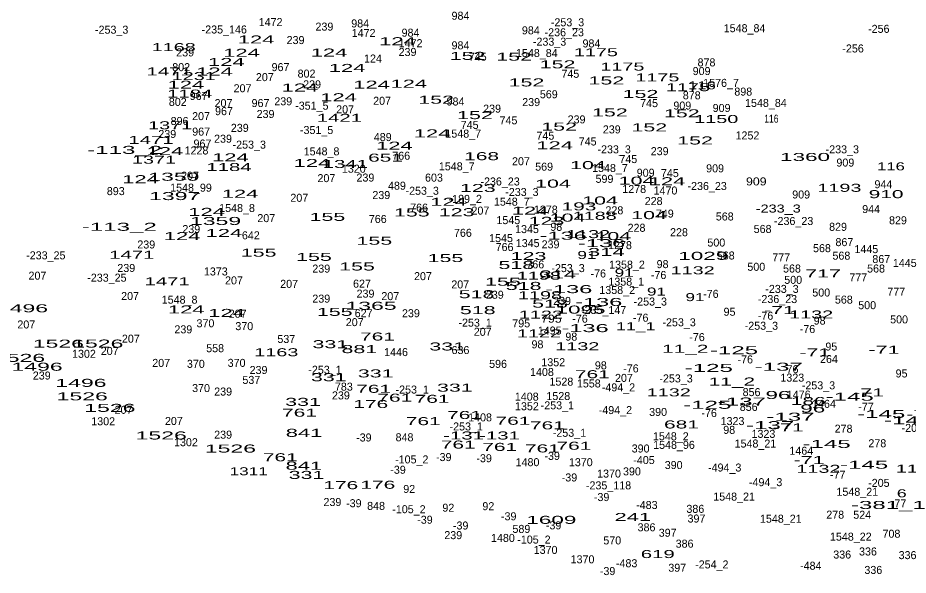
# Model space of a CAD drawing. Extents: x -660434 to -656144, y -997850 to -994016.
# Drawn here: x -659474 to -659029.2, y -994854.6 to -994576.2 of the extents above; entities that cross this region are included whole.
import ezdxf
from ezdxf.enums import TextEntityAlignment as Align

# ---------------------------------------------------------------- set-up
doc = ezdxf.new("R2010")
doc.units = 0
doc.header["$LTSCALE"] = 1.6
doc.layers.add('24', color=7, linetype='Continuous')

msp = doc.modelspace()

# ---------------------------------------------------------------- texts
at = {"layer": '24'}
for s, p in [('984', (-659252.897, -994577.15)), ('1472', (-659347.76, -994580.3)), ('239', (-659320.873, -994582.58)), ('984', (-659303.007, -994581)), ('-253_3', (-659199.422, -994580.42)), ('-253_3', (-659427.162, -994584.13)), ('-235_146', (-659370.905, -994584.02)), ('1472', (-659301.3, -994585.77)), ('984', (-659277.857, -994585.61)), ('984', (-659217.757, -994584.45)), ('-236_23', (-659201.057, -994585.42)), ('1548_84', (-659110.977, -994583.38)), ('-256', (-659043.91, -994583.7)), ('239', (-659335.293, -994589.31)), ('1472', (-659277.81, -994590.86)), ('984', (-659252.897, -994591.94)), ('-233_3', (-659208.392, -994590.11)), ('984', (-659187.467, -994590.99)), ('239', (-659390.463, -994595.47)), ('239', (-659279.353, -994595.28)), ('1548_84', (-659214.757, -994595.77)), ('-256', (-659056.77, -994593.5)), ('124', (-659296.62, -994598.52)), ('745', (-659244.277, -994597.6)), ('878', (-659129.993, -994600.46)), ('802', (-659392.431, -994602.84)), ('967', (-659342.813, -994602.82)), ('909', (-659132.432, -994604.79)), ('207', (-659350.647, -994607.82)), ('802', (-659329.801, -994606.06)), ('745', (-659198.007, -994606.15)), ('207', (-659361.787, -994613.39)), ('239', (-659327.023, -994611.43)), ('1576_7', (-659122.725, -994610.69)), ('967', (-659383.713, -994617.23)), ('569', (-659208.788, -994616.39)), ('878', (-659137.373, -994616.89)), ('898', (-659111.623, -994615.05)), ('802', (-659394.141, -994620.21)), ('207', (-659371.287, -994620.79)), ('967', (-659352.803, -994620.78)), ('239', (-659341.443, -994619.89)), ('-351_5', (-659327.166, -994622.09)), ('207', (-659292.067, -994619.64)), ('984', (-659255.387, -994619.99)), ('239', (-659217.593, -994620.29)), ('745', (-659158.677, -994620.81)), ('909', (-659142.082, -994622.03)), ('909', (-659122.442, -994623.23)), ('1548_84', (-659100.317, -994620.71)), ('207', (-659382.517, -994627.32)), ('967', (-659371.043, -994624.82)), ('239', (-659350.283, -994626.24)), ('207', (-659310.547, -994623.91)), ('239', (-659237.103, -994623.56)), ('896', (-659393.228, -994629.73)), ('745', (-659248.307, -994631.69)), ('745', (-659228.917, -994629.39)), ('239', (-659194.903, -994628.94)), ('239', (-659399.393, -994636.23)), ('967', (-659382.463, -994635.04)), ('239', (-659363.163, -994633.16)), ('-351_5', (-659324.766, -994634.24)), ('1548_7', (-659251.518, -994636.05)), ('239', (-659177.313, -994633.94)), ('967', (-659381.803, -994641)), ('239', (-659371.533, -994638.59)), ('489', (-659291.737, -994637.76)), ('745', (-659210.487, -994637.07)), ('745', (-659189.367, -994639.95)), ('1252', (-659109.53, -994636.94)), ('1228', (-659384.79, -994644.46)), ('-253_3', (-659358.422, -994641.54)), ('1548_8', (-659322.303, -994644.91)), ('-233_3', (-659176.132, -994643.9)), ('239', (-659153.393, -994644.81)), ('-233_3', (-659062.142, -994643.9)), ('766', (-659282.513, -994647.09)), ('207', (-659222.687, -994649.84)), ('745', (-659169.047, -994648.75)), ('1320', (-659306.214, -994653.57)), ('1548_7', (-659254.778, -994652.38)), ('569', (-659211.118, -994652.55)), ('1548_7', (-659178.218, -994653.22)), ('909', (-659125.712, -994653.39)), ('909', (-659060.622, -994650.51)), ('207', (-659388.037, -994657.07)), ('207', (-659319.877, -994658.29)), ('239', (-659300.393, -994657.99)), ('603', (-659266.147, -994658.02)), ('599', (-659180.968, -994658.62)), ('909', (-659160.382, -994655.58)), ('745', (-659148.307, -994655.77)), ('1548_99', (-659387.533, -994663.05)), ('489', (-659284.637, -994662.06)), ('-236_23', (-659233.117, -994659.95)), ('-236_23', (-659129.667, -994662.22)), ('944', (-659041.601, -994661.34)), ('893', (-659425.113, -994664.76)), ('239', (-659292.463, -994666.74)), ('-253_3', (-659272.022, -994664.59)), ('-233_3', (-659222.212, -994665.22)), ('1278', (-659166.116, -994663.71)), ('1470', (-659150.484, -994664.46)), ('909', (-659082.702, -994666.45)), ('207', (-659333.417, -994668.09)), ('-189_2', (-659250.522, -994668.64)), ('1548_7', (-659227.278, -994670.03)), ('228', (-659156.407, -994669.73)), ('1548_8', (-659364.523, -994673.2)), ('766', (-659273.583, -994673.01)), ('207', (-659242.937, -994674.5)), ('1278', (-659210.276, -994673.99)), ('228', (-659175.997, -994674.34)), ('749', (-659150.823, -994675.99)), ('944', (-659047.741, -994673.73)), ('207', (-659349.927, -994678.27)), ('766', (-659294.223, -994678.68)), ('1545', (-659228.994, -994679.25)), ('568', (-659120.883, -994677.43)), ('-236_23', (-659086.467, -994679.7)), ('829', (-659034.333, -994679.33)), ('239', (-659387.393, -994683.74)), ('766', (-659251.693, -994685.61)), ('1345', (-659219.674, -994683.73)), ('98', (-659205.023, -994682.61)), ('228', (-659164.947, -994683.08)), ('228', (-659143.737, -994685.29)), ('568', (-659101.963, -994683.66)), ('829', (-659064.283, -994682.6)), ('642', (-659357.637, -994686.85)), ('1545', (-659232.644, -994688.23)), ('239', (-659409.883, -994691.43)), ('766', (-659230.873, -994692.71)), ('1345', (-659219.334, -994690.74)), ('239', (-659207.913, -994691.35)), ('1278', (-659173.216, -994691.76)), ('500', (-659125.085, -994690.46)), ('568', (-659072.303, -994693.26)), ('867', (-659061.108, -994690.25)), ('1445', (-659050.139, -994693.74)), ('-233_25', (-659460.061, -994696.85)), ('568', (-659120.383, -994696.93)), ('777', (-659092.663, -994697.84)), ('568', (-659062.603, -994697.01)), ('867', (-659042.678, -994698.7)), ('239', (-659419.873, -994703.16)), ('766', (-659215.523, -994701.36)), ('-253_3', (-659199.162, -994703.22)), ('1358_2', (-659169.719, -994701.49)), ('98', (-659151.933, -994701.24)), ('500', (-659105.115, -994702.56)), ('568', (-659087.283, -994703.44)), ('568', (-659045.293, -994703.43)), ('1445', (-659030.939, -994700.65)), ('207', (-659464.237, -994706.99)), ('1373', (-659375.136, -994704.9)), ('239', (-659322.453, -994703.47)), ('207', (-659271.647, -994707.25)), ('-76', (-659184.065, -994705.91)), ('-76', (-659153.925, -994706.67)), ('-233_25', (-659429.541, -994708)), ('207', (-659366.057, -994709.36)), ('207', (-659338.497, -994711.09)), ('627', (-659302.108, -994711.01)), ('207', (-659253.017, -994711.38)), ('1358_1', (-659170.093, -994709.98)), ('500', (-659086.685, -994709.09)), ('777', (-659054.193, -994707.9)), ('239', (-659300.343, -994715.97)), ('239', (-659235.753, -994716.54)), ('1358_2', (-659174.609, -994714.16)), ('-76', (-659127.815, -994716.09)), ('-233_3', (-659092.282, -994713.62)), ('500', (-659072.665, -994715.43)), ('777', (-659035.183, -994715.01)), ('207', (-659417.967, -994717.17)), ('1548_8', (-659393.223, -994718.99)), ('239', (-659322.453, -994718.47)), ('207', (-659287.967, -994717.23)), ('239', (-659202.153, -994719.62)), ('-253_3', (-659158.072, -994719.93)), ('-236_23', (-659094.527, -994718.69)), ('568', (-659061.383, -994718.97)), ('-235_147', (-659181.365, -994724.16)), ('95', (-659118.483, -994725.03)), ('500', (-659049.725, -994721.75)), ('207', (-659364.207, -994726.01)), ('627', (-659301.288, -994725.76)), ('239', (-659277.663, -994725.77)), ('-76', (-659193.185, -994728.48)), ('-76', (-659162.855, -994727.99)), ('-76', (-659100.485, -994727.02)), ('98', (-659073.473, -994729.45)), ('500', (-659033.785, -994728.85)), ('207', (-659469.807, -994731.38)), ('239', (-659391.353, -994733.82)), ('370', (-659380.307, -994730.79)), ('370', (-659360.907, -994732.23)), ('207', (-659305.737, -994730.23)), ('-253_1', (-659245.586, -994730.48)), ('795', (-659222.568, -994730.81)), ('1495', (-659208.31, -994734.41)), ('-253_3', (-659143.672, -994730.3)), ('-253_3', (-659102.582, -994732.03)), ('-76', (-659079.555, -994733.65)), ('207', (-659417.587, -994738.49)), ('537', (-659339.913, -994738.63)), ('207', (-659241.797, -994735.03)), ('98', (-659197.523, -994737.46)), ('-76', (-659134.725, -994737.69)), ('558', (-659375.477, -994743.24)), ('98', (-659214.433, -994741.31)), ('95', (-659067.633, -994742.41)), ('1302', (-659441.004, -994746.03)), ('207', (-659428.147, -994744.64)), ('1446', (-659285.094, -994745.19)), ('636', (-659252.908, -994744.16)), ('207', (-659402.417, -994750.59)), ('370', (-659385.107, -994751.05)), ('370', (-659364.747, -994750.57)), ('596', (-659234.128, -994751.06)), ('1352', (-659206.55, -994750.25)), ('98', (-659182.783, -994751.81)), ('-76', (-659110.625, -994748.83)), ('264', (-659068.827, -994748.65)), ('239', (-659353.783, -994754.13)), ('-253_1', (-659320.586, -994754.01)), ('1408', (-659212.198, -994755.13)), ('-76', (-659167.745, -994753.34)), ('-76', (-659087.915, -994753.72)), ('95', (-659032.543, -994755.84)), ('239', (-659462.093, -994756.9)), ('537', (-659357.383, -994759.09)), ('1528', (-659202.49, -994759.93)), ('1558', (-659188.8, -994760.85)), ('207', (-659171.237, -994758.08)), ('-253_3', (-659145.212, -994758.34)), ('1323', (-659087.13, -994757.94)), ('370', (-659382.507, -994763.15)), ('239', (-659371.473, -994764.9)), ('783', (-659311.173, -994762.44)), ('-253_1', (-659277.006, -994763.9)), ('-494_2', (-659173.966, -994762.81)), ('856', (-659107.483, -994765.17)), ('-253_3', (-659074.052, -994761.8)), ('239', (-659312.643, -994766.82)), ('1408', (-659219.788, -994767.43)), ('1528', (-659204.03, -994767.14)), ('1476', (-659083.925, -994766.41)), ('207', (-659421.227, -994774.02)), ('1352', (-659219.71, -994772.24)), ('-253_1', (-659204.506, -994771.78)), ('-494_2', (-659175.506, -994774.15)), ('856', (-659108.923, -994772.57)), ('1464', (-659071.304, -994771.03)), ('-77', (-659050.315, -994772.51)), ('1408', (-659243.118, -994777.8)), ('390', (-659154.177, -994775.1)), ('-76', (-659128.675, -994775.62)), ('1302', (-659431.404, -994779.74)), ('207', (-659396.077, -994779.59)), ('-253_1', (-659250.026, -994782.33)), ('1323', (-659116.99, -994779.64)), ('278', (-659061.513, -994783.45)), ('-205', (-659027.179, -994783.06)), ('239', (-659371.473, -994786.44)), ('-39', (-659301.18, -994787.84)), ('848', (-659280.861, -994787.74)), ('-253_1', (-659198.466, -994785.5)), ('1548_2', (-659147.813, -994787.24)), ('98', (-659118.653, -994784.04)), ('1323', (-659101.55, -994786.02)), ('1302', (-659390.054, -994790.21)), ('1548_96', (-659146.233, -994791.54)), ('1548_21', (-659105.546, -994790.86)), ('278', (-659044.653, -994790.72)), ('390', (-659162.907, -994793.34)), ('1464', (-659082.634, -994794.46)), ('-105_2', (-659277.24, -994798.8)), ('-39', (-659261.25, -994797.63)), ('-39', (-659241.09, -994798.21)), ('1480', (-659219.408, -994800.18)), ('-39', (-659207.1, -994797.06)), ('1370', (-659192.8, -994800.2)), ('-405', (-659161.213, -994799.12)), ('-39', (-659284.1, -994803.97)), ('390', (-659167.237, -994804.78)), ('390', (-659146.397, -994801.61)), ('-494_3', (-659120.896, -994802.86)), ('-39', (-659198.45, -994807.81)), ('1370', (-659178.68, -994805.87)), ('-494_3', (-659100.446, -994810.16)), ('-77', (-659064.425, -994806.41)), ('92', (-659278.513, -994813.56)), ('-235_118', (-659178.929, -994811.77)), ('-205', (-659043.879, -994810.52)), ('-39', (-659182.38, -994817.61)), ('1548_21', (-659116.196, -994817.37)), ('1548_21', (-659054.656, -994814.97)), ('239', (-659316.883, -994820.09)), ('-39', (-659306.18, -994820.68)), ('848', (-659295.071, -994822.02)), ('92', (-659258.973, -994822.93)), ('92', (-659238.983, -994822.16)), ('-483', (-659159.789, -994821.56)), ('386', (-659135.573, -994823.49)), ('-77', (-659034.035, -994820.79)), ('-105_2', (-659278.65, -994823.68)), ('-39', (-659228.8, -994827.21)), ('278', (-659065.683, -994826.4)), ('524', (-659052.201, -994826.44)), ('-39', (-659270.65, -994828.94)), ('-39', (-659252.8, -994831.82)), ('-39', (-659206.38, -994831.73)), ('397', (-659134.998, -994828.33)), ('1548_21', (-659092.866, -994828.42)), ('239', (-659256.513, -994836.63)), ('589', (-659222.473, -994833.51)), ('386', (-659159.953, -994832.71)), ('397', (-659149.398, -994835.43)), ('708', (-659037.597, -994835.92)), ('1480', (-659231.698, -994838.02)), ('-105_2', (-659216.2, -994838.84)), ('570', (-659177.067, -994839.26)), ('386', (-659140.943, -994840.88)), ('1548_22', (-659057.902, -994837.38)), ('1370', (-659210.37, -994844)), ('336', (-659049.323, -994844.79)), ('1370', (-659191.93, -994848.7)), ('336', (-659062.193, -994846.32)), ('336', (-659029.553, -994846.61)), ('-39', (-659179.41, -994854.58)), ('-483', (-659169.879, -994850.66)), ('397', (-659144.598, -994852.91)), ('-254_2', (-659127.337, -994851.26)), ('-484', (-659077.903, -994851.91)), ('336', (-659046.643, -994854.01))]:
    msp.add_text(s, height=4, dxfattribs=at).set_placement(p, align=Align.CENTER)
for s, width, p in [('124', 2.05, (-659354.993, -994589.02)), ('124', 2.05, (-659284.383, -994589.89)), ('1168', 1.85, (-659396.159, -994592.83)), ('124', 2.05, (-659362.293, -994595.65)), ('124', 2.05, (-659318.563, -994595.55)), ('1175', 1.85, (-659185.239, -994595.37)), ('124', 2.05, (-659369.873, -994600.26)), ('152', 2, (-659249.317, -994597.21)), ('152', 2, (-659226.087, -994597.59)), ('1471', 1.9, (-659398.465, -994604.96)), ('124', 2.05, (-659375.773, -994605.01)), ('124', 2.05, (-659309.533, -994603.23)), ('152', 2, (-659204.387, -994601.43)), ('1175', 1.85, (-659171.999, -994602.57)), ('1231', 1.85, (-659386.164, -994607.28)), ('152', 2, (-659180.007, -994609.5)), ('1175', 1.85, (-659154.519, -994607.95)), ('124', 2.05, (-659390.083, -994611.6)), ('124', 2.05, (-659333.103, -994613.03)), ('124', 2.05, (-659297.343, -994611.59)), ('124', 2.05, (-659278.713, -994611.11)), ('152', 2, (-659219.937, -994610.46)), ('1175', 1.85, (-659139.249, -994612.85)), ('116', 1.55, (-659132.279, -994611.92)), ('1184', 1.9, (-659388.139, -994616.06)), ('124', 2.05, (-659313.813, -994617.88)), ('152', 2, (-659162.977, -994616.22)), ('152', 2, (-659265.067, -994619.1)), ('152', 2, (-659245.667, -994626.79)), ('152', 2, (-659178.277, -994625.44)), ('152', 2, (-659142.337, -994625.92)), ('1371', 1.85, (-659397.949, -994631.87)), ('1421', 1.9, (-659313.409, -994628.14)), ('1150', 1.85, (-659125.11, -994628.74)), ('116', 0.8, (-659097.591, -994628.58)), ('124', 2.05, (-659267.103, -994635.92)), ('152', 2, (-659203.617, -994632.55)), ('152', 2, (-659158.557, -994632.93)), ('1471', 1.9, (-659407.495, -994639.15)), ('152', 2, (-659135.707, -994639.46)), ('-113_2', 2.25, (-659420.647, -994644.17)), ('124', 2.05, (-659400.553, -994644.78)), ('124', 2.05, (-659285.923, -994642.07)), ('124', 2.05, (-659205.853, -994641.88)), ('1371', 1.85, (-659406.019, -994649.05)), ('124', 2.05, (-659367.853, -994647.89)), ('651', 1.95, (-659290.323, -994648.04)), ('168', 1.95, (-659242.323, -994647.31)), ('1360', 2.1, (-659080.759, -994647.7)), ('1184', 1.9, (-659368.549, -994652.73)), ('124', 2.05, (-659327.123, -994650.71)), ('1341', 1.9, (-659310.419, -994651.21)), ('104', 2, (-659189.229, -994651.78)), ('116', 1.55, (-659037.829, -994652.4)), ('124', 2.05, (-659412.743, -994658.8)), ('1359', 2.15, (-659396.083, -994657.58)), ('123', 2, (-659244.237, -994663.19)), ('104', 2, (-659206.699, -994661)), ('104', 2, (-659164.939, -994659.55)), ('124', 2.05, (-659149.693, -994659.84)), ('909', 1.15, (-659105.11, -994659.92)), ('1193', 1.85, (-659063.599, -994663.11)), ('1397', 2.15, (-659395.677, -994667.24)), ('124', 2.05, (-659363.013, -994666.1)), ('910', 1.95, (-659040.269, -994666.28)), ('124', 2.05, (-659258.843, -994670.11)), ('104', 2, (-659183.179, -994669.45)), ('124', 2.05, (-659379.713, -994675.13)), ('155', 2, (-659277.207, -994675.44)), ('123', 2, (-659254.797, -994675.29)), ('124', 2.05, (-659218.143, -994674.53)), ('193', 1.95, (-659193.703, -994672.39)), ('104', 2, (-659158.699, -994676.75)), ('-233_3', 1.35, (-659094.13, -994673.47)), ('1359', 2.15, (-659375.253, -994679.67)), ('155', 2, (-659319.357, -994677.64)), ('123', 2, (-659209.917, -994679.61)), ('104', 2, (-659199.409, -994678)), ('1188', 1.85, (-659185.844, -994677.09)), ('-113_2', 2.25, (-659423.337, -994682.58)), ('124', 2.05, (-659392.003, -994687.23)), ('124', 2.05, (-659371.093, -994685.67)), ('155', 2, (-659295.927, -994689.55)), ('-136', 2.2, (-659201.595, -994687.02)), ('1132', 1.85, (-659189.134, -994686.26)), ('104', 2, (-659176.559, -994687.22)), ('-136', 2.2, (-659182.395, -994690.76)), ('1471', 1.9, (-659417.095, -994696.58)), ('155', 2, (-659353.727, -994695.51)), ('155', 2, (-659326.077, -994697.62)), ('155', 2, (-659260.407, -994698.2)), ('123', 2, (-659218.897, -994697.18)), ('91', 1.6, (-659189.743, -994696.69)), ('314', 2.05, (-659180.043, -994695.18)), ('1029', 2.1, (-659131.599, -994697.1)), ('155', 2, (-659304.567, -994702.42)), ('518', 2, (-659224.987, -994701.66)), ('1198', 1.85, (-659213.739, -994707.01)), ('314', 2.05, (-659204.273, -994706.37)), ('91', 1.6, (-659171.123, -994705.53)), ('1132', 1.85, (-659136.904, -994704.32)), ('717', 2, (-659071.757, -994705.89)), ('1471', 1.9, (-659399.425, -994709.83)), ('155', 2, (-659231.707, -994710.01)), ('518', 2, (-659221.337, -994712.13)), ('518', 2, (-659244.857, -994716.26)), ('1198', 1.85, (-659213.169, -994716.76)), ('-136', 2.2, (-659198.815, -994713.72)), ('91', 1.6, (-659154.993, -994714.94)), ('518', 2, (-659208.177, -994720.96)), ('-136', 2.2, (-659183.835, -994720.15)), ('91', 1.6, (-659135.743, -994717.71)), ('1496', 2.15, (-659471.723, -994723.3)), ('124', 2.05, (-659389.913, -994723.89)), ('124', 2.05, (-659369.753, -994725.62)), ('155', 2, (-659315.707, -994725.09)), ('1365', 2.15, (-659297.593, -994722.04)), ('518', 2, (-659244.277, -994724.23)), ('1095', 2.1, (-659192.929, -994723.95)), ('-71', 2, (-659093.535, -994724.2)), ('1122', 1.85, (-659212.724, -994726.47)), ('795', 1.15, (-659207.5, -994728.5)), ('1132', 1.85, (-659077.714, -994726.4)), ('-136', 2.2, (-659190.655, -994733.2)), ('11_1', 1.65, (-659165.321, -994732.24)), ('761', 1.95, (-659294.347, -994737.41)), ('1122', 1.85, (-659213.674, -994735.83)), ('1526', 2.15, (-659453.783, -994740.97)), ('1526', 2.15, (-659434.083, -994740.93)), ('331', 2, (-659317.917, -994741.23)), ('331', 2, (-659259.547, -994742.38)), ('1132', 1.85, (-659194.534, -994742.26)), ('1163', 1.85, (-659344.889, -994745.26)), ('881', 2, (-659303.427, -994743.69)), ('11_2', 1.95, (-659140.625, -994743.52)), ('-125', 2.25, (-659116.251, -994744.26)), ('-71', 2, (-659075.865, -994745.33)), ('-71', 2, (-659041.305, -994743.99)), ('1526', 2.15, (-659473.173, -994748.08)), ('1496', 2.15, (-659464.433, -994752.5)), ('331', 2, (-659295.257, -994755.83)), ('761', 1.95, (-659187.017, -994756.23)), ('-125', 2.25, (-659128.831, -994753.09)), ('-137', 2.25, (-659093.905, -994752.49)), ('1496', 2.15, (-659442.533, -994760.56)), ('331', 2, (-659318.687, -994757.75)), ('11_2', 1.95, (-659117.325, -994759.89)), ('761', 1.95, (-659296.267, -994763.53)), ('331', 2, (-659255.707, -994762.94)), ('1132', 1.85, (-659148.834, -994765.3)), ('-71', 2, (-659048.985, -994765.31)), ('1526', 2.15, (-659441.873, -994767.29)), ('331', 2, (-659331.547, -994770.04)), ('761', 1.95, (-659285.707, -994767.95)), ('761', 1.95, (-659267.077, -994768.53)), ('-137', 2.25, (-659112.335, -994769.87)), ('96', 2.1, (-659094.291, -994766.62)), ('186', 1.95, (-659079.153, -994769.62)), ('-145', 2.25, (-659058.456, -994767.46)), ('1526', 2.15, (-659428.053, -994773.05)), ('176', 1.95, (-659297.717, -994771.12)), ('-125', 2.25, (-659129.591, -994771.53)), ('96', 2.1, (-659076.911, -994773.34)), ('761', 1.95, (-659333.317, -994775.44)), ('761', 1.95, (-659250.857, -994776.6)), ('-137', 2.25, (-659088.045, -994777.46)), ('-145', 2.25, (-659042.706, -994776.1)), ('-71', 2, (-659022.485, -994776.26)), ('761', 1.95, (-659271.497, -994779.67)), ('761', 1.95, (-659226.667, -994779.48)), ('761', 1.95, (-659209.477, -994781.78)), ('681', 1.95, (-659142.503, -994781.33)), ('-137', 2.25, (-659098.215, -994781.68)), ('-71', 2, (-659089.115, -994782.79)), ('-145', 2.25, (-659029.266, -994779.27)), ('1526', 2.15, (-659402.403, -994786.84)), ('841', 2.05, (-659331.053, -994785.52)), ('-131', 1.9, (-659251.347, -994786.84)), ('-131', 1.9, (-659233.397, -994786.85)), ('761', 1.95, (-659254.027, -994791.38)), ('761', 1.95, (-659196.227, -994791.96)), ('-145', 2.25, (-659069.976, -994791.08)), ('1526', 2.15, (-659367.833, -994793.37)), ('761', 1.95, (-659233.287, -994792.54)), ('761', 1.95, (-659211.977, -994793.3)), ('761', 1.95, (-659342.917, -994797.72)), ('-71', 2, (-659078.745, -994799.11)), ('1311', 1.6, (-659358.71, -994804.71)), ('841', 2.05, (-659331.153, -994801.94)), ('1132', 1.85, (-659074.084, -994803.49)), ('-145', 2.25, (-659051.256, -994801.45)), ('1192', 1.85, (-659024.409, -994803.39)), ('331', 2, (-659329.817, -994806.54)), ('176', 1.95, (-659312.697, -994811.65)), ('176', 1.95, (-659294.167, -994811.46)), ('6', 1.65, (-659032.446, -994815.73)), ('-381_1', 2.25, (-659039.117, -994821.55)), ('241', 2.05, (-659166.813, -994827.56)), ('1609', 2.1, (-659207.503, -994828.99)), ('619', 1.9, (-659154.327, -994846.08))]:
    msp.add_text(s, height=4, dxfattribs=dict(at, width=width)).set_placement(p, align=Align.CENTER)

doc.saveas('drawing.dxf')
